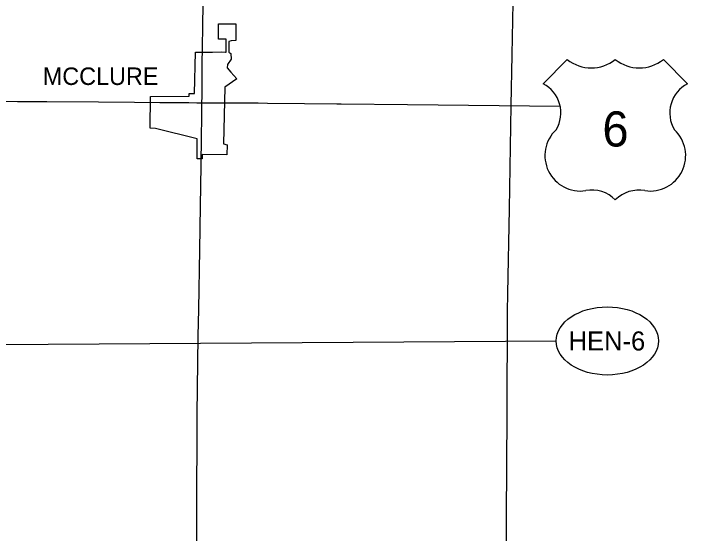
# Model space of a CAD drawing. Extents: x -62 to 810, y 0 to 440.
# Drawn here: x 408.1 to 507, y 199.3 to 275.7 of the extents above; entities that cross this region are included whole.
import ezdxf

# ---------------------------------------------------------------- set-up
doc = ezdxf.new("R2010")
doc.units = 0
for name, color, linetype in [('DV_X_Corp_Line', 7, 'Continuous'), ('GM_X_Corporation_Text', 7, 'Continuous'), ('GM_X_County', 7, 'Continuous'), ('GM_X_State_Route', 7, 'Continuous'), ('PV_P_Text', 7, 'Continuous'), ('SH_Data', 7, 'Continuous')]:
    doc.layers.add(name, color=color, linetype=linetype)

msp = doc.modelspace()

# ---------------------------------------------------------------- linework, layer by layer
at = {"layer": 'DV_X_Corp_Line'}
msp.add_lwpolyline([(434.812, 269.985), (435.848, 269.963), (437.312, 270.001), (438.647, 270.007), (439.222, 269.995), (439.331, 269.993), (439.33, 271.873), (438.189, 271.869), (438.188, 274.151), (440.754, 274.159), (440.755, 271.698), (440.084, 271.649), (439.736, 271.561), (439.737, 270), (440.021, 269.797), (440.079, 268.973), (439.547, 268.15), (439.469, 267.66), (440.003, 267.026), (440.894, 266.074), (439.12, 264.825), (438.957, 256.53), (439.466, 256.393), (439.42, 254.897), (435.806, 254.943), (435.806, 254.346), (435.094, 254.344), (435.092, 257.277), (428.951, 258.78), (428.195, 258.802), (428.232, 263.461), (433.89, 263.526), (433.899, 263.906), (434.69, 263.907)], close=True, dxfattribs=at)
at = {"layer": 'GM_X_County'}
msp.add_lwpolyline([(480.484, 186.821), (480.475, 201.492), (480.476, 201.722), (480.541, 216.902), (480.604, 231.893), (480.652, 234.564), (480.876, 246.964), (481.151, 262.151), (481.286, 269.58), (481.424, 277.213), (481.698, 292.342), (481.869, 301.768), (481.958, 306.701), (482.019, 309.241), (482.36, 323.527), (482.48, 329.733), (482.513, 331.512), (482.759, 344.728), (482.899, 352.282)], dxfattribs=at)
at = {"layer": 'GM_X_State_Route'}
for points in [[(435.862, 271.194), (435.886, 273.283), (435.938, 277.659), (436.032, 285.694), (436.146, 292.879), (436.227, 297.927), (436.278, 300.389), (436.365, 304.577), (436.402, 307.873)], [(435.848, 269.963), (435.862, 271.194)], [(435.788, 263.284), (435.797, 264.478), (435.805, 265.581), (435.813, 266.689), (435.817, 267.249), (435.823, 267.798), (435.836, 268.969), (435.848, 269.963)], [(364.198, 263.037), (368.891, 262.972), (374.978, 262.881), (379.814, 262.808), (390.079, 262.732), (390.242, 262.754), (392.655, 262.906), (393.215, 262.916), (394.306, 262.896), (397.877, 262.859), (405.457, 262.782), (408.703, 262.749), (413.048, 262.725), (420.595, 262.684), (425.883, 262.655), (429.596, 262.616), (429.597, 262.616)], [(435.783, 262.558), (435.783, 262.558), (435.785, 262.747), (435.788, 263.284)], [(429.597, 262.616), (430.394, 262.609), (431.912, 262.594), (433.842, 262.576), (435.006, 262.565), (435.783, 262.558), (436.764, 262.555), (437.763, 262.552), (439.675, 262.547), (439.708, 262.546)], [(435.753, 260.152), (435.758, 260.574), (435.77, 261.535), (435.783, 262.558)], [(439.708, 262.546), (443.282, 262.536), (444.015, 262.529), (444.047, 262.529)], [(444.047, 262.529), (445.393, 262.515)], [(445.393, 262.515), (450.827, 262.459), (455.567, 262.407)], [(455.567, 262.407), (456.178, 262.4), (465.941, 262.304), (488.321, 262.079)], [(435.73, 258.348), (435.746, 259.619), (435.753, 260.15), (435.753, 260.152)], [(435.716, 257.296), (435.723, 257.823), (435.73, 258.344), (435.73, 258.348)], [(435.709, 256.694), (435.715, 257.143), (435.716, 257.296)], [(435.678, 254.289), (435.709, 256.688), (435.709, 256.694)], [(435.321, 232.256), (435.486, 240.97), (435.58, 247.373), (435.666, 253.347), (435.678, 254.28), (435.678, 254.289)], [(434.911, 171.574), (434.911, 171.574), (434.955, 186.634), (434.958, 187.552), (435.015, 199.607), (435.023, 201.766), (435.081, 216.798), (435.245, 228.285), (435.321, 232.256)]]:
    msp.add_lwpolyline(points, dxfattribs=at)
at = {"layer": 'PV_P_Text'}
for p, q in [((489.37, 268.896), (485.825, 265.351)), ((507.008, 265.351), (503.462, 268.896))]:
    msp.add_line(p, q, dxfattribs=at)
for centre, radius, start, end in [((492.893, 273.375), 5.699, 231.81301, 308.18697), ((499.939, 273.375), 5.699, 231.81301, 308.18697), ((483.608, 261.071), 4.82, 329.11751, 62.61081), ((509.225, 261.071), 4.82, 117.38919, 210.88249), ((491.291, 254.794), 5.2, 133.00455, 278.72816), ((501.541, 254.794), 5.2, 261.27184, 46.99545), ((493.037, 245.102), 4.652, 43.41772, 101.87423), ((499.892, 244.793), 4.937, 79.96126, 134.74679)]:
    msp.add_arc(centre, radius, start, end, dxfattribs=at)
at = {"layer": 'SH_Data'}
msp.add_line((487.742, 227.57), (359.697, 226.704), dxfattribs=at)
msp.add_ellipse((495.242, 227.592), major_axis=(7.5, 0), ratio=0.666667, dxfattribs=at)

# ---------------------------------------------------------------- texts
at = {"layer": 'GM_X_Corporation_Text'}
msp.add_text('MCCLURE', height=2.565, rotation=0.00001, dxfattribs=at).set_placement((412.438, 265.167))
at = {"layer": 'PV_P_Text'}
msp.add_text('6', height=5.162, dxfattribs=at).set_placement((494.522, 256.13))
at = {"layer": 'SH_Data'}
msp.add_text('HEN-6', height=2.8, dxfattribs=at).set_placement((489.569, 226.192))

doc.saveas('drawing.dxf')
